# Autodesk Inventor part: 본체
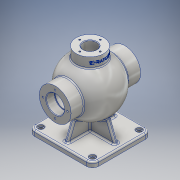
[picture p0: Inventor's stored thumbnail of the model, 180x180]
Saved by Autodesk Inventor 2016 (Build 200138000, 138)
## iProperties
Created: 2017-01
Part Number: 본체
Material: 알루미늄 6061
Document SubType Name: Modeling
Designer: Administrator
Density: 2.7 g/cm^3
Appearance: 알루미늄 - 평지
Mass: 1504.01 g
Surface Area: 1153.86 cm^2
Volume: 557.04 cm^3
Author: Administrator
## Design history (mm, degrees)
sketch "스케치1"
  geometry: L1 (-62.5, 57.5)-(62.5, 57.5); L2 (62.5, 57.5)-(62.5, -57.5); L3 (62.5, -57.5)-(-62.5, -57.5); L4 (-62.5, -57.5)-(-62.5, 57.5); 1 further point
  constraints: 8 end point, 2 parallel, 1 horizontal, 1 perpendicular
  dimensions: "d0" = 125 distance of L1.start L1.end; "d1" = 115 distance of L1.end L2.end; "d2" = 57.5 distance from line of point (0, 0) L1; "d3" = 62.5 distance from line of point (0, 0) L4
extrude "돌출1" new body sketch "스케치1" distance "d4" = 10; taper "d5" = 0 deg
fillet "모깎기1" dims "d6" = 12
sketch "스케치2"
  geometry: A1 r 12 centre (-50.5, 45.5) between (-50.5, 57.5) and (-62.5, 45.5) reference; 2 further points
  constraints: 1 coincident
hole "구멍1" sketch "스케치2" at (-50.5, 45.5) diameter "d7" = 8; stored, may be unused: countersink angle "d11" = 90 deg, drill point angle "d13" = 118 deg; dims "d8" = 6, "d9" = 12, "d10" = 3, "d12" = 8
sketch "스케치4"
  geometry: L1 (-45.5, 0)-(45.5, 0) reference; L2 (0, 85)-(68, 85); L3 (68, 85)-(68, 116); L4 (68, 116)-(42.988, 116); L5 (0, 85)-(-68, 85); L6 (-68, 85)-(-68, 116); L7 (-68, 116)-(-42.988, 116); A1 r 53 centre (0, 85) between (42.988, 116) and (-42.988, 116); 1 further point
  constraints: 12 end point, 2 horizontal, 2 parallel, 2 perpendicular, 2 point on circle, 1 centre point
revolve "회전1" sketch "스케치4" stored, may be unused: angle "d26" = 90 deg
sketch "스케치5"
  geometry: L1 (-45.5, 10)-(45.5, 10) reference; L2 (25.353, 64.816)-(47.5, 10); L3 (57.5, 0)-(57.5, 10) reference; L4 (-51.5, 10)-(-39.5, 10) reference; L5 (-47.5, 10)-(-25.353, 64.816); L6 (-57.5, 10)-(-57.5, 0) reference; L7 (-25.353, 64.816)-(25.353, 64.816); L8 (-47.5, 10)-(47.5, 10)
  constraints: 8 end point, 2 horizontal, 2 point on line
  dimensions: "d45" = 10 distance from line of L3 L2.end; "d46" = 22 deg angle of L3 L2; "d47" = 22 deg angle of L6 L5; "d48" = 10 distance from line of L6 L5.start
fillet "모깎기4" dims "d38" = 3
extrude "돌출3" join sketch "스케치5" stored distance "d49" = 8; taper "d50" = 0 deg
sketch "스케치7"
  geometry: L1 (-50.5, 10)-(50.5, 10) reference; L2 (62.5, 10)-(62.5, 0) reference; L3 (50.5, 10)-(-50.5, 10) reference; L4 (-37.379, 47.426)-(-52.5, 10); L5 (-62.5, 0)-(-62.5, 10) reference; L6 (37.379, 47.426)-(52.5, 10); A1 r 53 centre (0, 85) between (4, 32.151) and (-4, 32.151) reference; 1 further point
  constraints: 4 end point, 2 point on circle, 2 point on line
  dimensions: "d52" = 10 distance from line of L5 L4.end; "d53" = 22 deg angle of L5 L4; "d55" = 10 distance from line of L2 L6.end; "d57" = 22 deg angle of L6 L2
feature "리브2" dims "d64" = 1, "d65" = 8, "d66" = 0, "d67" = 0, "d68" = 1, "d69" = 1
feature "리브3" dims "d70" = 1, "d71" = 8, "d72" = 0, "d73" = 0, "d74" = 1, "d75" = 1
fillet "모깎기5" dims "d76" = 3
fillet "모깎기6" dims "d77" = 3
fillet "모깎기7" dims "d78" = 3
sketch "스케치8"
  geometry: L1 (-68, 54)-(-68, 116) reference; L2 (68, 85)-(-68, 85); L3 (-68, 85)-(-68, 102.5); L4 (68, 102.5)-(68, 85); L5 (45.5, 0)-(-45.5, 0) reference; L6 (39.278, 102.5)-(68, 102.5); L7 (-50.25, 102.5)-(-50.25, 103.5); L8 (-50.25, 103.5)-(-52, 103.5); L9 (-52, 103.5)-(-52, 102.5); L10 (-68, 102.5)-(-52, 102.5); L11 (-50.25, 102.5)-(-39.278, 102.5); A1 r 43 centre (0, 85) between (39.278, 102.5) and (-39.278, 102.5); 1 further point
  constraints: 18 end point, 4 parallel, 2 horizontal, 2 point on circle, 2 vertical, 1 centre point, 1 midpoint, 1 perpendicular, 1 point on line
  dimensions: "d79" = 85 distance between parallel lines of L5 L2; "d81" = 86 diameter of A1; "d85" = 16 distance of L3.end L9.end; "d86" = 1.75 distance of L7.end L8.end; "d87" = 136 distance of L2.start L2.end; "d143" = 17.5 distance between parallel lines of L2 L6
revolve "회전2" sketch "스케치8" stored, may be unused: angle "d82" = 90 deg
chamfer "모따기1" distance "d88" = 1; stored, may be unused: second distance "d89" = 2, angle "d90" = 45 deg
sketch "스케치9"
  geometry: 2 further points
hole "구멍2" sketch "스케치9" at (0, -22.5) diameter "d92" = 3.242; stored, may be unused: countersink angle "d96" = 90 deg, drill point angle "d98" = 118 deg; dims "d93" = 12, "d94" = 12, "d95" = 3, "d97" = 15
sketch "스케치10"
  geometry: 2 further points
hole "구멍3" sketch "스케치10" at (0, 24) diameter "d103" = 3.242; stored, may be unused: countersink angle "d107" = 90 deg, drill point angle "d109" = 118 deg; dims "d104" = 16, "d105" = 12, "d106" = 3, "d108" = 19
node "작업 평면1"
sketch "스케치11"
  geometry: C1 r 27 at (0, 0); 1 further point
  constraints: 1 centre point, 1 coincident
  dimensions: "d114" = 54 diameter of C1
extrude "돌출4" join sketch "스케치11" stored distance "d115" = 8; taper "d116" = 0 deg
sketch "스케치12"
  geometry: C1 r 13 at (0, 0); 1 further point
  constraints: 1 centre point, 1 coincident
  dimensions: "d117" = 26 diameter of C1
extrude "돌출5" cut sketch "스케치12" distance "d118" = 58.75; taper "d119" = 0 deg
sketch "스케치13"
  geometry: 2 further points
hole "구멍4" sketch "스케치13" at (0, 20) diameter "d121" = 3.242; stored, may be unused: countersink angle "d125" = 90 deg, drill point angle "d127" = 118 deg; dims "d122" = 9, "d123" = 12, "d124" = 3, "d126" = 11
node "작업 평면2"
sketch "스케치15"
  geometry: L1 (-20.81, 138.177)-(20.81, 138.177); L2 (20.81, 138.177)-(20.81, 141.823); L3 (20.81, 141.823)-(-20.81, 141.823); L4 (-20.81, 141.823)-(-20.81, 138.177); L5 (27, 150)-(-27, 150) reference; 4 further points
  constraints: 2 midpoint, 2 other
  dimensions: "d135" = 27 horizontal distance of point (0, 140) L5.end; "d142" = 10 distance from line of L5 point (20.81, 140)
feature "엠보싱1" sketch "스케치15" dims "d4" = 10, "d136" = 0.5, "d137" = 0
fillet "모깎기8" dims "d138" = 3
chamfer "모따기2" distance "d139" = 1; stored, may be unused: second distance "d140" = 2, angle "d141" = 45 deg
node "솔리드1"
pattern_linear "직사각형 패턴1" dims "d16" = 101, "d19" = 91
pattern_circular "원형 패턴2" dims angle "d100" = 360 deg
pattern_circular "원형 패턴3" dims angle "d111" = 360 deg
pattern_circular "원형 패턴4" dims angle "d129" = 360 deg
other parameters: "d80" = 17.5, "d131" = 92.75
